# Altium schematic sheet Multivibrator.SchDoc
size A4; Author: Michał Wojna; CompanyName: AGH; Revision: 1; SheetNumber: 1; SheetTotal: 1
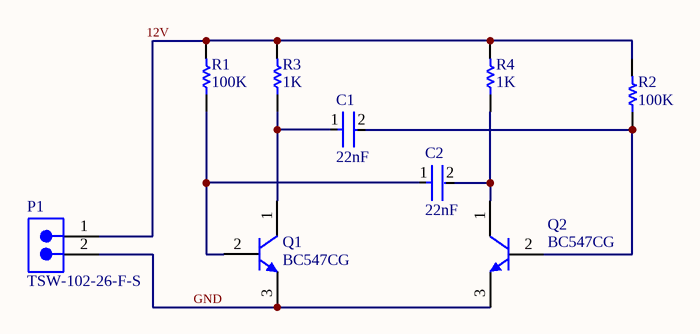
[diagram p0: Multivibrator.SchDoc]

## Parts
C1  22nF  [FP-C0603C-CF-MFG]
C2  22nF  [FP-C0603C-CF-MFG]
P1  TSW-102-26-F-S  [SMTC-TSW-102-26-XX-S]
Q1  BC547CG  [ONSC-TO-92-3-29-11]
Q2  BC547CG  [ONSC-TO-92-3-29-11]
R1  100K  [RESC2013X70X40NL20T20]
R2  100K  [RESC2013X70X40NL20T20]
R3  1K  [RESC2013X70X40LL20T20]
R4  1K  [RESC2013X70X40LL20T20]

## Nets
12V: P1.1 R1.2 R2.2 R3.2 R4.2
GND: P1.2 Q1.3(E) Q2.3(E)
NetC1_1: C1.1 Q1.1(C) R3.1
NetC1_2: C1.2 Q2.2(B) R2.1
NetC2_1: C2.1 Q1.2(B) R1.1
NetC2_2: C2.2 Q2.1(C) R4.1

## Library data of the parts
C1 C2 = CMP-2006-03745-2: CAP CER 0.022UF 16V 5% X7R 0603; Manufacturer Part Number: C0603C223J4RACTU; Manufacturer: KEMET; Tolerance: 0.05; Automotive Grade: Grade 1; Temperature Coefficient: 30ppm/°C; Description: C0603 22,000 pF X7R 30ppm/°C 5.00% 16 V; Capacitance: 22,000 pF; Material: Ceramic; Value: 22,000 pF
P1 = CMP-1024-00329-1: 0.025" SQ Post Header, Through-hole, Vertical, -55 to 125 degC, 2.54 mm Pitch, 2-Pin, Male, RoHS; Manufacturer: Samtec; Pitch: 2.54 mm
Q1 Q2 = CMP-1048-01464-1: Amplifier Transistor, NPN Silicon, 3-Pin TO-92, Pb-Free, Bulk Box; Manufacturer: On Semiconductor; IC Continuous (A): 0.1; fT Min (MHz): 150
R1 R2 = CMP-2001-00338-1: Part Number: ERJ-6GEYJ104V; Manufacturer: Panasonic
R3 R4 = CMP-2001-00477-1: Manufacturer: Panasonic; Part Number: ERJ-P06J102V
